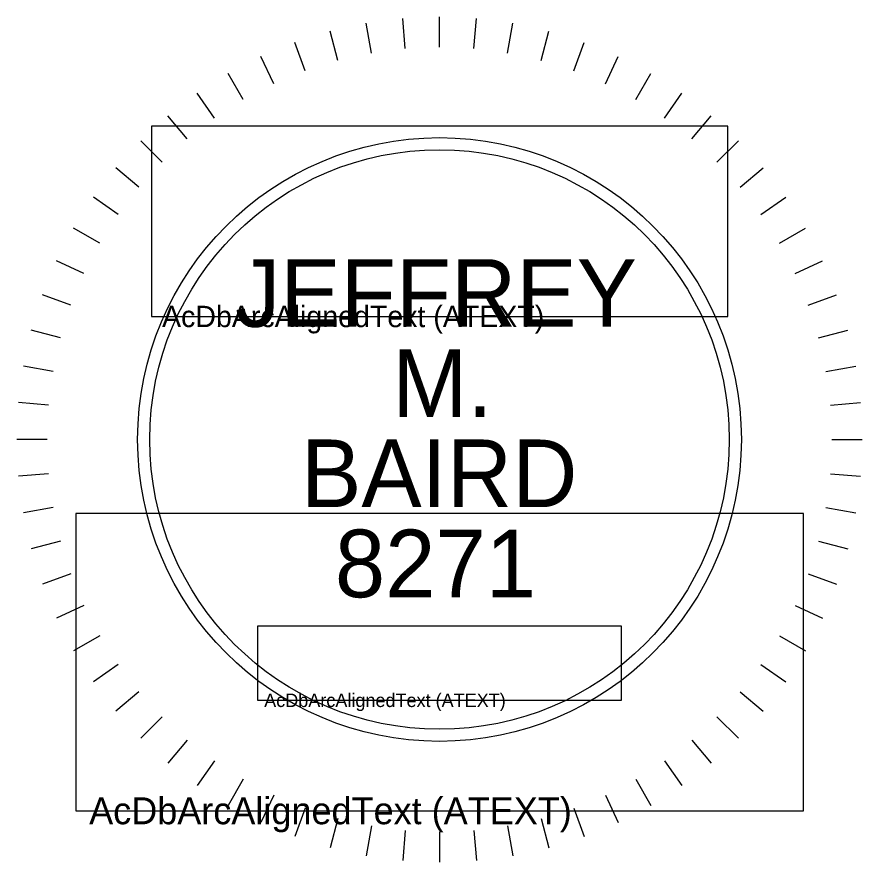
# Model space of a CAD drawing. Extents: x 0 to 104, y 0 to 37.
# Drawn here: x 41.767 to 43.517, y 2.298 to 4.048 of the extents above; entities that cross this region are included whole.
import ezdxf

# ---------------------------------------------------------------- set-up
doc = ezdxf.new("R2010")
doc.units = 0
doc.layers.add('Default', color=7, linetype='Continuous')
doc.layers.add('SH_Text', color=7, linetype='Continuous')

# ---------------------------------------------------------------- blocks, each defined once
blk = doc.blocks.new('PS_Stamp_JMB')
at = {"layer": 'Default'}
for p, q in [((-0.07167, 0.40648), (-0.07719, 0.43775)), ((-0.03597, 0.41118), (-0.03874, 0.44281)), ((0, 0.41275), (0, 0.4445)), ((0.03597, 0.41118), (0.03874, 0.44281)), ((0.07167, 0.40648), (0.07719, 0.43775)), ((-0.10683, 0.39869), (-0.11505, 0.42935)), ((0.10683, 0.39869), (0.11505, 0.42935)), ((-0.14117, 0.38786), (-0.15203, 0.41769)), ((0.14117, 0.38786), (0.15203, 0.41769)), ((-0.17444, 0.37408), (-0.18785, 0.40285)), ((0.17444, 0.37408), (0.18785, 0.40285)), ((-0.20638, 0.35745), (-0.22225, 0.38495)), ((0.20637, 0.35745), (0.22225, 0.38495)), ((-0.23674, 0.33811), (-0.25495, 0.36411)), ((0.23674, 0.33811), (0.25495, 0.36411)), ((-0.26531, 0.31618), (-0.28572, 0.34051)), ((0.26531, 0.31618), (0.28572, 0.34051)), ((-0.29186, 0.29186), (-0.31431, 0.31431)), ((0.29186, 0.29186), (0.31431, 0.31431)), ((-0.31618, 0.26531), (-0.34051, 0.28572)), ((0.31618, 0.26531), (0.34051, 0.28572)), ((-0.33811, 0.23674), (-0.36411, 0.25495)), ((0.33811, 0.23674), (0.36411, 0.25495)), ((-0.35745, 0.20637), (-0.38495, 0.22225)), ((0.35745, 0.20637), (0.38495, 0.22225)), ((-0.37408, 0.17444), (-0.40285, 0.18785)), ((0.37408, 0.17444), (0.40285, 0.18785)), ((-0.38786, 0.14117), (-0.41769, 0.15203)), ((0.38786, 0.14117), (0.41769, 0.15203)), ((-0.39869, 0.10683), (-0.42935, 0.11505)), ((0.39869, 0.10683), (0.42935, 0.11505)), ((-0.40648, 0.07167), (-0.43775, 0.07719)), ((0.40648, 0.07167), (0.43775, 0.07719)), ((-0.41118, 0.03597), (-0.44281, 0.03874)), ((0.41118, 0.03597), (0.44281, 0.03874)), ((-0.41275, 0), (-0.4445, 0)), ((0.41275, 0), (0.4445, 0)), ((-0.41118, -0.03597), (-0.44281, -0.03874)), ((0.41118, -0.03597), (0.44281, -0.03874)), ((-0.40648, -0.07167), (-0.43775, -0.07719)), ((0.40648, -0.07167), (0.43775, -0.07719)), ((-0.39869, -0.10683), (-0.42935, -0.11505)), ((0.39869, -0.10683), (0.42935, -0.11505)), ((-0.38786, -0.14117), (-0.41769, -0.15203)), ((0.38786, -0.14117), (0.41769, -0.15203)), ((-0.37408, -0.17444), (-0.40285, -0.18785)), ((0.37408, -0.17444), (0.40285, -0.18785)), ((-0.35745, -0.20638), (-0.38495, -0.22225)), ((0.35745, -0.20638), (0.38495, -0.22225)), ((-0.33811, -0.23674), (-0.36411, -0.25495)), ((0.33811, -0.23674), (0.36411, -0.25495)), ((-0.31618, -0.26531), (-0.34051, -0.28572)), ((0.31618, -0.26531), (0.34051, -0.28572)), ((-0.29186, -0.29186), (-0.31431, -0.31431)), ((0.29186, -0.29186), (0.31431, -0.31431)), ((-0.26531, -0.31618), (-0.28572, -0.34051)), ((0.26531, -0.31618), (0.28572, -0.34051)), ((-0.23674, -0.33811), (-0.25495, -0.36411)), ((0.23674, -0.33811), (0.25495, -0.36411)), ((-0.20638, -0.35745), (-0.22225, -0.38495)), ((0.20637, -0.35745), (0.22225, -0.38495)), ((-0.17444, -0.37408), (-0.18785, -0.40285)), ((0.17444, -0.37408), (0.18785, -0.40285)), ((-0.14117, -0.38786), (-0.15203, -0.41769)), ((0.14117, -0.38786), (0.15203, -0.41769)), ((-0.10683, -0.39869), (-0.11505, -0.42935)), ((0.10683, -0.39869), (0.11505, -0.42935)), ((-0.07167, -0.40648), (-0.07719, -0.43775)), ((0.07167, -0.40648), (0.07719, -0.43775)), ((-0.03597, -0.41118), (-0.03874, -0.44281)), ((0, -0.41275), (0, -0.4445)), ((0.03597, -0.41118), (0.03874, -0.44281))]:
    blk.add_line(p, q, dxfattribs=at)
for points in [[(-0.30309, 0.12941), (0.30309, 0.12941), (0.30309, 0.32957), (-0.30309, 0.32957), (-0.30309, 0.12941)], [(-0.38269, -0.39052), (0.38269, -0.39052), (0.38269, -0.07783), (-0.38269, -0.07783), (-0.38269, -0.39052)], [(-0.19153, -0.27432), (0.19153, -0.27432), (0.19153, -0.19639), (-0.19153, -0.19639), (-0.19153, -0.27432)]]:
    blk.add_lwpolyline(points, dxfattribs=at)
for radius in [0.3175, 0.3175, 0.3175, 0.3048, 0.3048, 0.3048]:
    blk.add_circle((0, 0), radius, dxfattribs=at)
for s, height, p in [('JEFFREY', 0.07112, (-0.21505, 0.11853)), ('AcDbArcAlignedText (ATEXT)', 0.0224514, (-0.29187, 0.11819)), (' M.', 0.07112, (-0.0762, 0.02371)), ('BAIRD', 0.07112, (-0.14563, -0.07112)), ('8271', 0.07112, (-0.11007, -0.16595)), ('AcDbArcAlignedText (ATEXT)', 0.0141872, (-0.18443, -0.28141)), ('AcDbArcAlignedText (ATEXT)', 0.0283475, (-0.36852, -0.4047))]:
    blk.add_text(s, height=height, dxfattribs=at).set_placement(p)

msp = doc.modelspace()

# ---------------------------------------------------------------- block references
at = {"layer": 'SH_Text', "xscale": 1.9685000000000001, "yscale": 1.9685000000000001}
msp.add_blockref('PS_Stamp_JMB', (42.6423, 3.1727), dxfattribs=at)

doc.saveas('drawing.dxf')
